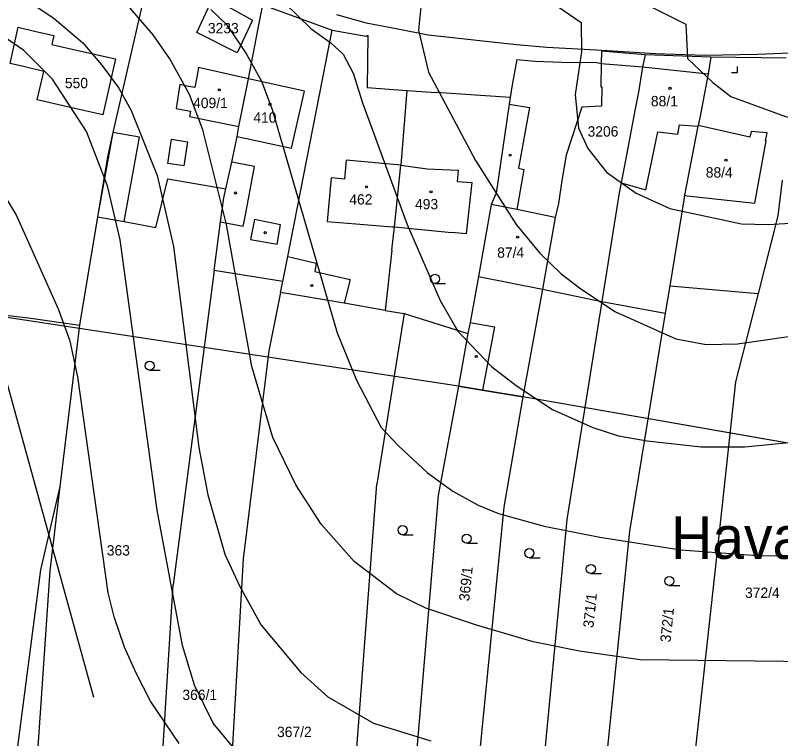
# Model space of a CAD drawing. Extents: x -555860 to -552701, y -1187050 to -1182291.
# Drawn here: x -554839.8 to -554714.1, y -1184624.3 to -1184505.6 of the extents above; entities that cross this region are included whole.
import ezdxf

# ---------------------------------------------------------------- set-up
doc = ezdxf.new("R2010")
doc.units = 0
for name, color, linetype in [('CYKLISTI_stav', 7, 'Continuous'), ('LEG_2b', 7, 'Continuous'), ('Level 25', 7, 'Continuous'), ('Level 32', 7, 'Continuous'), ('Level 40', 7, 'Continuous'), ('Level 41', 7, 'Continuous'), ('navrh_BV', 7, 'Continuous'), ('Parcelní čísla', 7, 'Continuous'), ('Poz předměty', 7, 'Continuous')]:
    doc.layers.add(name, color=color, linetype=linetype)

msp = doc.modelspace()

# ---------------------------------------------------------------- linework, layer by layer
at = {"layer": 'CYKLISTI_stav'}
for p, q in [((-554809.69, -1184514.22), (-554809.98, -1184515.79)), ((-554801.48, -1184516.06), (-554809.69, -1184514.22)), ((-554736.79, -1184514.11), (-554726.04, -1184515.23)), ((-554809.98, -1184515.79), (-554810.3, -1184517.5)), ((-554792.33, -1184518.07), (-554801.48, -1184516.06)), ((-554812.77, -1184516.97), (-554813.37, -1184520.91)), ((-554811.65, -1184517.25), (-554812.77, -1184516.97)), ((-554810.3, -1184517.5), (-554811.65, -1184517.25)), ((-554794.42, -1184527.45), (-554792.33, -1184518.07)), ((-554758.71, -1184520.2), (-554755.38, -1184520.78)), ((-554813.37, -1184520.91), (-554811.02, -1184521.35)), ((-554811.02, -1184521.35), (-554811.19, -1184522.26)), ((-554755.38, -1184520.78), (-554757.15, -1184530.73)), ((-554811.19, -1184522.26), (-554803.06, -1184523.89)), ((-554730.98, -1184525.13), (-554730.7, -1184523.58)), ((-554730.7, -1184523.58), (-554727.7, -1184523.83)), ((-554719.16, -1184525.63), (-554727.68, -1184523.73)), ((-554823.78, -1184524.85), (-554826.28, -1184538.7)), ((-554819.4, -1184525.64), (-554823.78, -1184524.85)), ((-554736.23, -1184534.29), (-554734.28, -1184524.77)), ((-554734.28, -1184524.77), (-554730.98, -1184525.13)), ((-554718.95, -1184524.71), (-554719.16, -1184525.63)), ((-554716.32, -1184524.91), (-554718.95, -1184524.71)), ((-554716.61, -1184526.2), (-554716.32, -1184524.91)), ((-554821.9, -1184539.49), (-554819.4, -1184525.64)), ((-554814.72, -1184529.93), (-554814.13, -1184525.98)), ((-554814.13, -1184525.98), (-554811.53, -1184526.37)), ((-554811.53, -1184526.37), (-554812.13, -1184530.32)), ((-554803.38, -1184525.49), (-554794.42, -1184527.45)), ((-554718.36, -1184536.43), (-554716.47, -1184526.23)), ((-554716.47, -1184526.23), (-554716.61, -1184526.2)), ((-554812.13, -1184530.32), (-554814.72, -1184529.93)), ((-554800.53, -1184530.42), (-554804.23, -1184529.75)), ((-554802.12, -1184538.96), (-554800.53, -1184530.42)), ((-554785.45, -1184529.41), (-554785.73, -1184532.49)), ((-554776.51, -1184530.2), (-554785.45, -1184529.41)), ((-554776.51, -1184530.2), (-554772.18, -1184530.81)), ((-554772.18, -1184530.81), (-554767.09, -1184531.06)), ((-554767.09, -1184531.06), (-554767.25, -1184532.88)), ((-554756.28, -1184530.92), (-554757.43, -1184537.47)), ((-554757.15, -1184530.73), (-554756.28, -1184530.92)), ((-554787.93, -1184532.29), (-554788.6, -1184539.46)), ((-554785.73, -1184532.49), (-554787.93, -1184532.29)), ((-554767.25, -1184532.88), (-554764.85, -1184533.08)), ((-554764.85, -1184533.08), (-554765.73, -1184541.49)), ((-554740.3, -1184533.1), (-554736.23, -1184534.29)), ((-554729.9, -1184535.16), (-554729.46, -1184535.24)), ((-554729.46, -1184535.24), (-554718.36, -1184536.43)), ((-554757.43, -1184537.47), (-554761.67, -1184536.66)), ((-554751.12, -1184538.78), (-554757.43, -1184537.47)), ((-554802.36, -1184540.24), (-554802.12, -1184538.96)), ((-554800.53, -1184539.15), (-554801.19, -1184542.39)), ((-554796.22, -1184540.01), (-554800.53, -1184539.15)), ((-554806.09, -1184539.54), (-554802.36, -1184540.24)), ((-554796.81, -1184543.18), (-554796.22, -1184540.01)), ((-554788.6, -1184539.46), (-554777.85, -1184540.32)), ((-554777.85, -1184540.32), (-554777.55, -1184540.34)), ((-554777.55, -1184540.34), (-554768.14, -1184541.26)), ((-554765.73, -1184541.49), (-554768.14, -1184541.26)), ((-554801.19, -1184542.39), (-554796.81, -1184543.18)), ((-554795.06, -1184545.23), (-554790.41, -1184546.32)), ((-554790.41, -1184546.32), (-554790.61, -1184547.69)), ((-554790.61, -1184547.69), (-554784.78, -1184548.99)), ((-554784.78, -1184548.99), (-554785.78, -1184552.89)), ((-554763.75, -1184548.49), (-554753.24, -1184550.58)), ((-554765.1, -1184556.01), (-554761.11, -1184556.76)), ((-554761.11, -1184556.76), (-554763.08, -1184567.16))]:
    msp.add_line(p, q, dxfattribs=at)
msp.add_lwpolyline([(-554839.33, -1184507.6), (-554836.65, -1184508.21), (-554833.44, -1184508.94), (-554833.78, -1184510.41), (-554829.01, -1184511.5), (-554823.34, -1184512.79), (-554825.42, -1184521.98), (-554831.24, -1184520.65), (-554836.18, -1184519.52), (-554835.1, -1184514.83), (-554838.24, -1184514.11), (-554840.65, -1184513.56), (-554839.33, -1184507.6)], dxfattribs=at)
at = {"layer": 'Level 25'}
for p, q in [((-554721.19, -1184515.04), (-554721.19, -1184514.04)), ((-554722.19, -1184515.04), (-554721.19, -1184515.04)), ((-554770.89, -1184549.63), (-554769.14, -1184549.63)), ((-554817.73, -1184563.88), (-554815.98, -1184563.88)), ((-554776.19, -1184590.86), (-554774.44, -1184590.86)), ((-554765.67, -1184592.25), (-554763.92, -1184592.25)), ((-554755.37, -1184594.64), (-554753.62, -1184594.64)), ((-554745.28, -1184597.22), (-554743.53, -1184597.22)), ((-554732.4, -1184599.21), (-554730.65, -1184599.21))]:
    msp.add_line(p, q, dxfattribs=at)
for centre, radius in [((-554806.3, -1184517.85), 0.175), ((-554732.29, -1184517.61), 0.175), ((-554797.98, -1184520.24), 0.175), ((-554758.52, -1184528.58), 0.175), ((-554723.1, -1184529.39), 0.175), ((-554782.13, -1184533.78), 0.175), ((-554803.63, -1184534.78), 0.175), ((-554771.53, -1184534.59), 0.175), ((-554798.77, -1184541.3), 0.175), ((-554757.3, -1184542.03), 0.175), ((-554770.89, -1184548.88), 0.75), ((-554791.09, -1184549.98), 0.175), ((-554764.1, -1184561.61), 0.175), ((-554817.73, -1184563.13), 0.75), ((-554776.19, -1184590.11), 0.75), ((-554765.67, -1184591.5), 0.75), ((-554755.37, -1184593.89), 0.75), ((-554745.28, -1184596.47), 0.75), ((-554732.4, -1184598.46), 0.75)]:
    msp.add_circle(centre, radius, dxfattribs=at)
at = {"layer": 'Level 32'}
msp.add_lwpolyline([(-554690.37, -1184660.23), (-554684.77, -1184643.87), (-554675.11, -1184635.77), (-554668.37, -1184620.38), (-554665.78, -1184591.72), (-554664.62, -1184584.28), (-554756.45, -1184568.21), (-554763.08, -1184567.16), (-554766.99, -1184566.47), (-554857.78, -1184552.7)], dxfattribs=at)
at = {"layer": 'Level 40'}
for points in [[(-554773.1, -1184503.09), (-554773.59, -1184508.07), (-554771.95, -1184514.97), (-554764.2, -1184529.43), (-554757.55, -1184539.97), (-554753.66, -1184544.68), (-554750.14, -1184548.06), (-554747.15, -1184550.36), (-554741.32, -1184554.25), (-554731.34, -1184558.69), (-554726.35, -1184559.66), (-554721.22, -1184559.52), (-554708.6, -1184557.72)], [(-554803.03, -1184626.9), (-554807.32, -1184621.77), (-554810.37, -1184615.55), (-554812.32, -1184609.02), (-554816.48, -1184586.83), (-554822.58, -1184542.46), (-554824.66, -1184533.59), (-554828.12, -1184524.71), (-554833.67, -1184516.12), (-554838.38, -1184511.4), (-554843.36, -1184508.04)]]:
    msp.add_lwpolyline(points, dxfattribs=at)
at = {"layer": 'Level 41'}
for points in [[(-554765.17, -1184494.21), (-554746.87, -1184506.82), (-554746.84, -1184511.65), (-554747.84, -1184518.61), (-554747.29, -1184524.16), (-554745.76, -1184527.49), (-554742.71, -1184531.37), (-554737.86, -1184534.84), (-554732.31, -1184537.33), (-554720.53, -1184539.83), (-554716.18, -1184539.98), (-554711.65, -1184539.69)], [(-554797.73, -1184501.45), (-554791.24, -1184507.8), (-554787.95, -1184510.19), (-554785.97, -1184512), (-554784.32, -1184515.13), (-554782.78, -1184520), (-554775.43, -1184539.97), (-554770.03, -1184552.45), (-554767.11, -1184557.44), (-554761.57, -1184563.26), (-554757.57, -1184566.38), (-554751.58, -1184570.33), (-554744.93, -1184573.24), (-554740.73, -1184574.63), (-554736.06, -1184575.46), (-554727.18, -1184576.43), (-554719.97, -1184576.43), (-554708.88, -1184575.32)], [(-554742.02, -1184500.86), (-554729.67, -1184507.09), (-554729.4, -1184512.73), (-554725.24, -1184516.67), (-554722.32, -1184518.93), (-554713.32, -1184522.22), (-554710.1, -1184522.89), (-554706.66, -1184523.19), (-554701.85, -1184522.72), (-554697.79, -1184521.8), (-554694.43, -1184520.58), (-554691.13, -1184518.61), (-554688.98, -1184516.45), (-554687.8, -1184515.01), (-554686.19, -1184509.5), (-554686.19, -1184504.67)], [(-554838.94, -1184502.39), (-554833.39, -1184506.13), (-554828.68, -1184510.16), (-554825.57, -1184513.81), (-554822.77, -1184517.61), (-554820.77, -1184521.25), (-554816.48, -1184531.92), (-554813.84, -1184543.57), (-554809.68, -1184576.57), (-554808.16, -1184584.34), (-554805.38, -1184594.04), (-554802.94, -1184599.38), (-554799.42, -1184605.69), (-554792.9, -1184613.46), (-554788.47, -1184617.48), (-554780.98, -1184621.77), (-554771.55, -1184624.69)], [(-554680.59, -1184612.07), (-554737.16, -1184611.38), (-554747.15, -1184609.99), (-554754.76, -1184608.45), (-554764.06, -1184605.69), (-554772.38, -1184602.92), (-554777.2, -1184600.53), (-554784.13, -1184595.25), (-554789.58, -1184589.15), (-554793.74, -1184582.67), (-554797.48, -1184574.91), (-554800.95, -1184563.26), (-554805.11, -1184539.97), (-554808.99, -1184524.44), (-554811.21, -1184518.61), (-554814.4, -1184512.79), (-554817.16, -1184508.86), (-554820.91, -1184504.47)], [(-554807.71, -1184504.7), (-554805.03, -1184507.22), (-554801.81, -1184512), (-554799.34, -1184516.45), (-554797.62, -1184521.11), (-554786.94, -1184557.72), (-554783.75, -1184565.48), (-554779.73, -1184573.24), (-554776.87, -1184576.28), (-554772.1, -1184580.73), (-554767.96, -1184583.7), (-554763.79, -1184586), (-554760.46, -1184587.39), (-554752.95, -1184589.48), (-554743.82, -1184591.27), (-554730.51, -1184593.35), (-554717.2, -1184594.32), (-554709.99, -1184594.18)], [(-554812.87, -1184625.1), (-554817.58, -1184618.17), (-554819.94, -1184613.57), (-554821.88, -1184609.29), (-554823.57, -1184604.33), (-554824.52, -1184600.42), (-554829.51, -1184564.93), (-554830.8, -1184559.12), (-554832.7, -1184553.83), (-554839.63, -1184538.3), (-554842.41, -1184533.87)], [(-554851.19, -1184545.99), (-554846.89, -1184550.59), (-554843.65, -1184557.16), (-554826.96, -1184617.53)]]:
    msp.add_lwpolyline(points, dxfattribs=at)
at = {"layer": 'navrh_BV'}
for p, q in [((-554817.33, -1184496.67), (-554823.78, -1184524.85)), ((-554809.99, -1184508.43), (-554807.34, -1184502.76)), ((-554807.34, -1184502.76), (-554800.83, -1184506.44)), ((-554799.68, -1184506.65), (-554799.15, -1184503.89)), ((-554799.15, -1184503.89), (-554787.74, -1184508.06)), ((-554800.83, -1184506.44), (-554803.35, -1184511.79)), ((-554787.07, -1184505.52), (-554782.18, -1184506.84)), ((-554801.48, -1184516.06), (-554799.68, -1184506.65)), ((-554782.18, -1184506.84), (-554777.27, -1184507.8)), ((-554777.27, -1184507.8), (-554771.99, -1184508.81)), ((-554803.35, -1184511.79), (-554809.99, -1184508.43)), ((-554795.06, -1184545.23), (-554787.74, -1184508.06)), ((-554787.74, -1184508.06), (-554782.17, -1184509.03)), ((-554782.17, -1184509.03), (-554781.89, -1184508.87)), ((-554781.89, -1184508.87), (-554781.99, -1184517.46)), ((-554771.99, -1184508.81), (-554757.49, -1184510.4)), ((-554757.49, -1184510.4), (-554752.52, -1184510.88)), ((-554752.52, -1184510.88), (-554744.35, -1184511.28)), ((-554744.35, -1184511.28), (-554734.66, -1184511.87)), ((-554743.56, -1184511.5), (-554743.58, -1184513.52)), ((-554740.32, -1184511.8), (-554743.56, -1184511.5)), ((-554736.37, -1184512.11), (-554740.32, -1184511.8)), ((-554736.37, -1184512.11), (-554736.79, -1184514.11)), ((-554725.56, -1184512.5), (-554736.37, -1184512.11)), ((-554734.66, -1184511.87), (-554726.63, -1184512.18)), ((-554726.63, -1184512.18), (-554717.9, -1184511.99)), ((-554725.56, -1184512.5), (-554726.04, -1184515.23)), ((-554713.22, -1184512.66), (-554725.56, -1184512.5)), ((-554717.9, -1184511.99), (-554709.32, -1184511.66)), ((-554757.41, -1184512.9), (-554758.2, -1184517.05)), ((-554757.41, -1184512.9), (-554754.4, -1184513.13)), ((-554754.4, -1184513.13), (-554750.1, -1184513.32)), ((-554750.1, -1184513.32), (-554744.31, -1184513.39)), ((-554744.31, -1184513.39), (-554743.58, -1184513.52)), ((-554743.58, -1184513.52), (-554743.63, -1184517.34)), ((-554736.79, -1184514.11), (-554737.46, -1184518.24)), ((-554726.04, -1184515.23), (-554726.62, -1184518.43)), ((-554803.06, -1184523.89), (-554801.48, -1184516.06)), ((-554781.99, -1184517.46), (-554775.48, -1184517.97)), ((-554758.2, -1184517.05), (-554758.55, -1184519.09)), ((-554743.63, -1184517.34), (-554743.48, -1184517.38)), ((-554743.48, -1184517.38), (-554743.53, -1184520.56)), ((-554775.48, -1184517.97), (-554776.51, -1184530.2)), ((-554775.48, -1184517.97), (-554770.67, -1184518.29)), ((-554758.55, -1184519.09), (-554770.67, -1184518.29)), ((-554758.55, -1184519.09), (-554758.71, -1184520.2)), ((-554737.46, -1184518.24), (-554738.05, -1184521.26)), ((-554726.62, -1184518.43), (-554727.41, -1184522.46)), ((-554758.71, -1184520.2), (-554760.85, -1184534.8)), ((-554746.78, -1184520.72), (-554749.34, -1184528.56)), ((-554743.53, -1184520.56), (-554746.78, -1184520.72)), ((-554738.05, -1184521.26), (-554739.01, -1184526.23)), ((-554727.41, -1184522.46), (-554727.68, -1184523.73)), ((-554803.38, -1184525.49), (-554803.06, -1184523.89)), ((-554727.7, -1184523.83), (-554729.9, -1184535.16)), ((-554727.68, -1184523.73), (-554727.7, -1184523.83)), ((-554823.78, -1184524.85), (-554824.65, -1184528.84)), ((-554804.23, -1184529.75), (-554803.38, -1184525.49)), ((-554739.01, -1184526.23), (-554739.82, -1184530.56)), ((-554824.65, -1184528.84), (-554826.28, -1184538.7)), ((-554749.34, -1184528.56), (-554750.03, -1184532.76)), ((-554805.21, -1184534.13), (-554804.23, -1184529.75)), ((-554777.55, -1184540.34), (-554776.51, -1184530.2)), ((-554739.82, -1184530.56), (-554740.3, -1184533.1)), ((-554816.69, -1184540.43), (-554814.74, -1184532.45)), ((-554814.74, -1184532.45), (-554805.21, -1184534.13)), ((-554750.03, -1184532.76), (-554750.62, -1184536.52)), ((-554713.88, -1184532.7), (-554714.58, -1184538.55)), ((-554805.54, -1184535.59), (-554805.21, -1184534.13)), ((-554740.3, -1184533.1), (-554740.61, -1184534.75)), ((-554760.85, -1184534.8), (-554761.67, -1184536.66)), ((-554740.61, -1184534.75), (-554743.48, -1184552.61)), ((-554729.9, -1184535.16), (-554730.02, -1184535.9)), ((-554806.09, -1184539.54), (-554805.54, -1184535.59)), ((-554761.67, -1184536.66), (-554763.75, -1184548.49)), ((-554750.62, -1184536.52), (-554751.12, -1184538.78)), ((-554730.02, -1184535.9), (-554732.34, -1184550.01)), ((-554826.28, -1184538.7), (-554829.26, -1184556.45)), ((-554826.28, -1184538.7), (-554821.9, -1184539.49)), ((-554751.12, -1184538.78), (-554753.24, -1184550.58)), ((-554714.58, -1184538.55), (-554717.82, -1184551.28)), ((-554821.9, -1184539.49), (-554816.69, -1184540.43)), ((-554807.13, -1184547.52), (-554806.09, -1184539.54)), ((-554777.97, -1184544.17), (-554777.55, -1184540.34)), ((-554777.97, -1184544.17), (-554779.06, -1184554.04)), ((-554795.86, -1184549.3), (-554795.06, -1184545.23)), ((-554807.13, -1184547.52), (-554813.88, -1184599.07)), ((-554795.86, -1184549.3), (-554807.13, -1184547.52)), ((-554763.75, -1184548.49), (-554765.1, -1184556.01)), ((-554796.22, -1184551.11), (-554795.86, -1184549.3)), ((-554732.34, -1184550.01), (-554733.08, -1184554.52)), ((-554732.34, -1184550.01), (-554717.82, -1184551.28)), ((-554796.22, -1184551.11), (-554798.15, -1184560.69)), ((-554785.78, -1184552.89), (-554796.22, -1184551.11)), ((-554753.24, -1184550.58), (-554756.45, -1184568.21)), ((-554753.24, -1184550.58), (-554743.48, -1184552.61)), ((-554717.82, -1184551.28), (-554721.52, -1184565.78)), ((-554779.06, -1184554.04), (-554785.78, -1184552.89)), ((-554743.48, -1184552.61), (-554749.23, -1184588.38)), ((-554743.48, -1184552.61), (-554733.08, -1184554.52)), ((-554846.45, -1184554.17), (-554837.25, -1184555.34)), ((-554779.06, -1184554.04), (-554775.95, -1184554.56)), ((-554837.25, -1184555.34), (-554829.26, -1184556.45)), ((-554775.95, -1184554.56), (-554780.4, -1184582.57)), ((-554775.95, -1184554.56), (-554765.5, -1184557.84)), ((-554733.08, -1184554.52), (-554738.95, -1184590.26)), ((-554829.26, -1184556.45), (-554832.46, -1184582.92)), ((-554765.1, -1184556.01), (-554765.5, -1184557.84)), ((-554765.5, -1184557.84), (-554766.99, -1184566.47)), ((-554798.15, -1184560.69), (-554802.36, -1184594.79)), ((-554766.99, -1184566.47), (-554770.33, -1184584.42)), ((-554766.99, -1184566.47), (-554763.08, -1184567.16)), ((-554721.52, -1184565.78), (-554724.51, -1184593.01)), ((-554763.08, -1184567.16), (-554756.45, -1184568.21)), ((-554756.45, -1184568.21), (-554759.57, -1184586.36)), ((-554832.46, -1184582.92), (-554835.63, -1184596.62)), ((-554832.46, -1184582.92), (-554834.13, -1184596.78)), ((-554784.98, -1184642.26), (-554780.4, -1184582.57)), ((-554770.33, -1184584.42), (-554774.16, -1184629.32)), ((-554759.57, -1184586.36), (-554763.88, -1184629.9)), ((-554749.23, -1184588.38), (-554754.31, -1184641.83)), ((-554738.95, -1184590.26), (-554744.14, -1184640.97)), ((-554724.51, -1184593.01), (-554729.69, -1184640.28)), ((-554802.36, -1184594.79), (-554805.97, -1184657.16)), ((-554835.63, -1184596.62), (-554839.73, -1184627.77)), ((-554834.13, -1184596.78), (-554836.27, -1184628.03)), ((-554815.79, -1184630.36), (-554813.88, -1184599.07))]:
    msp.add_line(p, q, dxfattribs=at)
at = {"layer": 'Poz předměty'}
for points in [[(-554743.58, -1184513.52), (-554736.79, -1184514.11)], [(-554766.99, -1184566.47), (-554857.78, -1184552.7), (-554861.33, -1184552.85), (-554891.41, -1184554.08)], [(-554664.62, -1184584.28), (-554675.39, -1184582.4), (-554756.45, -1184568.21)]]:
    msp.add_lwpolyline(points, dxfattribs=at)

# ---------------------------------------------------------------- texts
at = {"layer": 'LEG_2b'}
for s, p in [('3233', (-554808.16, -1184508.59)), ('550', (-554831.65, -1184517.59)), ('409/1', (-554810.59, -1184520.86)), ('88/1', (-554735.42, -1184520.56)), ('410', (-554800.7, -1184523.25)), ('3206', (-554745.82, -1184525.53)), ('88/4', (-554726.41, -1184532.26)), ('462', (-554784.94, -1184536.69)), ('493', (-554774.15, -1184537.46)), ('87/4', (-554760.66, -1184545.41)), ('363', (-554824.77, -1184594.27)), ('372/4', (-554719.96, -1184601.23)), ('366/1', (-554812.35, -1184617.98)), ('367/2', (-554796.81, -1184624.06))]:
    msp.add_text(s, height=1.7, dxfattribs=at).set_placement(p)
for s, p in [('369/1', (-554765.26, -1184601.83)), ('371/1', (-554744.87, -1184606.2)), ('372/1', (-554732.21, -1184608.58))]:
    msp.add_text(s, height=1.7, rotation=84, dxfattribs=at).set_placement(p)
at = {"layer": 'Parcelní čísla'}
msp.add_text('Havale', height=7, dxfattribs=at).set_placement((-554732.1, -1184594.82))

doc.saveas('drawing.dxf')
